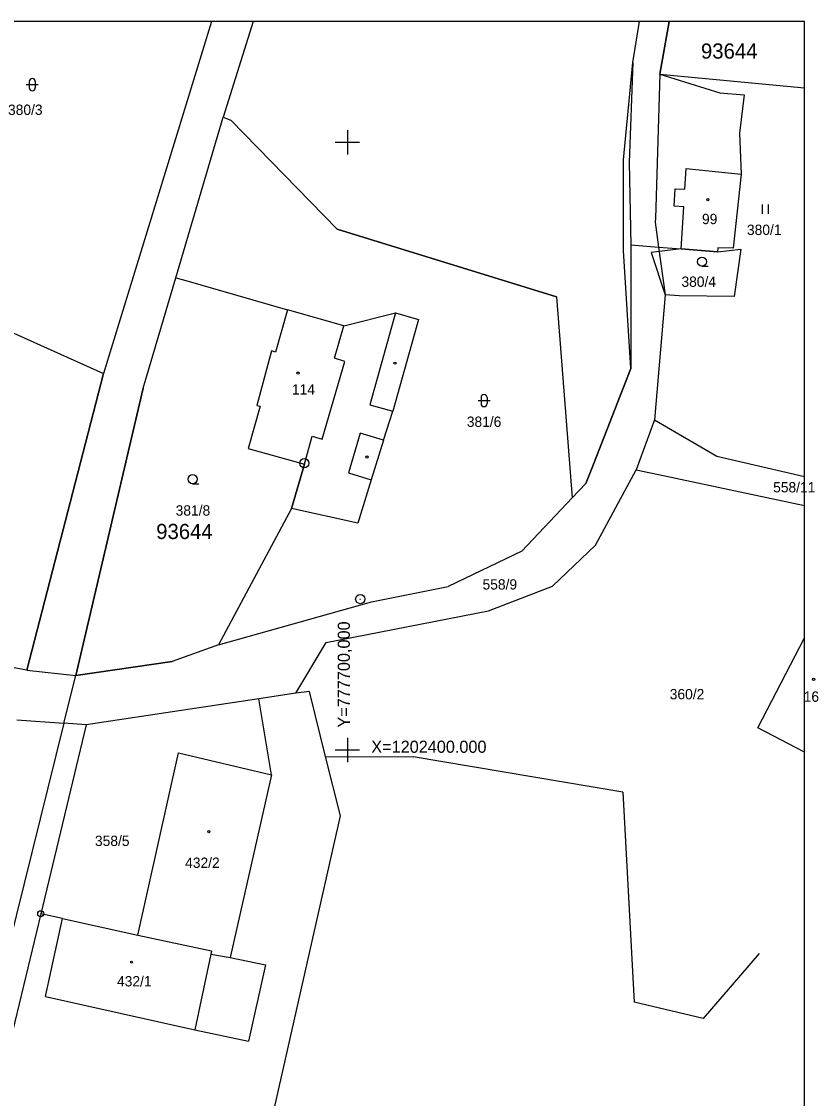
# Model space of a CAD drawing. Extents: x -778045 to -768365, y -1202571 to -1202059.
# Drawn here: x -777753.6 to -777622.5, y -1202457.4 to -1202280.1 of the extents above; entities that cross this region are included whole.
import ezdxf

# ---------------------------------------------------------------- set-up
doc = ezdxf.new("R2010")
doc.units = 0
for name, color, linetype in [('BPEJ', 7, 'Continuous'), ('Katastr_Hranice parcel', 7, 'Continuous'), ('Katastr_Parcelní čísla', 7, 'Continuous'), ('Katastr_Slučkované čáry', 7, 'Continuous'), ('Katastr_Značky kultur', 7, 'Continuous'), ('čtvercová síť', 7, 'Continuous')]:
    doc.layers.add(name, color=color, linetype=linetype)

# ---------------------------------------------------------------- blocks, each defined once
blk = doc.blocks.new('C691')
at = {"layer": 'čtvercová síť'}
for p, q in [((0, 0.5), (0, -0.5)), ((-0.5, 0), (0.5, 0))]:
    blk.add_line(p, q, dxfattribs=at)

msp = doc.modelspace()

# ---------------------------------------------------------------- linework, layer by layer
at = {"layer": 'BPEJ'}
for points in [[(-777715.51, -1202280.12), (-777720.45, -1202295.86), (-777719.2, -1202296.33), (-777701.71, -1202314.27), (-777665.58, -1202325.46), (-777663.01, -1202358.54), (-777660.78, -1202356.18), (-777659.91, -1202353.96), (-777653.34, -1202337.23), (-777654.57, -1202317.8), (-777654.55, -1202302.89), (-777653.05, -1202286.88), (-777651.96, -1202280.12)], [(-777647.08, -1202280.12), (-777648.6, -1202288.78), (-777638.72, -1202291.84), (-777634.69, -1202292.2), (-777635.48, -1202298.47), (-777635.2, -1202305.22), (-777636.54, -1202317.41), (-777639.06, -1202317.35), (-777639.1, -1202318), (-777645.06, -1202317.53), (-777650.01, -1202318.12), (-777647.71, -1202325.12), (-777649.49, -1202345.7), (-777639.21, -1202351.67), (-777624.79, -1202354.99)], [(-777788.3, -1202316.49), (-777774.01, -1202322.88), (-777740.14, -1202338.03), (-777752.8, -1202386.89), (-777773.14, -1202383.15), (-777779.27, -1202388.61), (-777811.7, -1202375.6), (-777805.7, -1202356.3), (-777793.87, -1202330.63), (-777788.3, -1202316.49)], [(-777728.24, -1202322.3), (-777726.98, -1202322.66), (-777709.85, -1202327.57), (-777711.82, -1202334.53), (-777712.49, -1202334.34), (-777714.9, -1202343.3), (-777714.35, -1202343.45), (-777716.32, -1202350.41), (-777707.07, -1202352.95), (-777709.23, -1202360.29), (-777721.22, -1202382.72), (-777728.85, -1202385.43), (-777744.73, -1202387.77), (-777733.6, -1202340.49), (-777728.24, -1202322.3)]]:
    msp.add_lwpolyline(points, dxfattribs=at)
at = {"layer": 'Defpoints'}
for p, q in [((-777624.79, -1202280.12), (-778044.79, -1202280.12)), ((-777624.79, -1202569.12), (-777624.79, -1202280.12))]:
    msp.add_line(p, q, dxfattribs=at)
at = {"layer": 'Katastr_Hranice parcel'}
for p, q in [((-777648.6, -1202288.78), (-777624.79, -1202291.01)), ((-777714.61, -1202391.58), (-777743, -1202395.86)), ((-777708.49, -1202390.66), (-777714.61, -1202391.58)), ((-777712.49, -1202404.11), (-777714.61, -1202391.58)), ((-777743, -1202395.86), (-777750.49, -1202426.97)), ((-777750.49, -1202426.97), (-777772.39, -1202517.89)), ((-777746.91, -1202427.75), (-777750.49, -1202426.97))]:
    msp.add_line(p, q, dxfattribs=at)
for points in [[(-777722.39, -1202280.12), (-777740.14, -1202338.03)], [(-777715.51, -1202280.12), (-777720.45, -1202295.86)], [(-777653.05, -1202286.88), (-777651.96, -1202280.12)], [(-777648.6, -1202288.78), (-777647.08, -1202280.12)], [(-777653.05, -1202286.88), (-777653.66, -1202303.32)], [(-777648.6, -1202288.78), (-777649.33, -1202312.52)], [(-777648.6, -1202288.78), (-777638.72, -1202291.84)], [(-777638.72, -1202291.84), (-777634.69, -1202292.2)], [(-777634.69, -1202292.2), (-777635.48, -1202298.47)], [(-777728.24, -1202322.3), (-777720.45, -1202295.86)], [(-777720.45, -1202295.86), (-777719.2, -1202296.33)], [(-777701.71, -1202314.27), (-777719.2, -1202296.33)], [(-777635.48, -1202298.47), (-777635.2, -1202305.22)], [(-777653.66, -1202303.32), (-777653.34, -1202316.88)], [(-777635.2, -1202305.22), (-777636.54, -1202317.41)], [(-777649.33, -1202312.52), (-777649.34, -1202313.17), (-777648.79, -1202317.24)], [(-777665.58, -1202325.46), (-777701.71, -1202314.27)], [(-777653.34, -1202316.88), (-777653.34, -1202337.23)], [(-777653.34, -1202316.88), (-777648.79, -1202317.24)], [(-777648.79, -1202317.24), (-777645.06, -1202317.53)], [(-777648.79, -1202317.24), (-777647.71, -1202325.12)], [(-777645.06, -1202317.53), (-777639.1, -1202318)], [(-777639.06, -1202317.35), (-777639.1, -1202318)], [(-777639.1, -1202318), (-777635.26, -1202317.6)], [(-777636.54, -1202317.41), (-777639.06, -1202317.35)], [(-777635.26, -1202317.6), (-777636.36, -1202325.39)], [(-777774.01, -1202322.88), (-777740.14, -1202338.03)], [(-777733.6, -1202340.49), (-777728.24, -1202322.3)], [(-777728.24, -1202322.3), (-777726.98, -1202322.66)], [(-777726.98, -1202322.66), (-777709.85, -1202327.57)], [(-777665.58, -1202325.46), (-777663.01, -1202358.54)], [(-777647.71, -1202325.12), (-777649.49, -1202345.7)], [(-777645.43, -1202325.29), (-777647.71, -1202325.12)], [(-777636.36, -1202325.39), (-777645.43, -1202325.29)], [(-777709.85, -1202327.57), (-777711.82, -1202334.53)], [(-777700.6, -1202330.22), (-777709.85, -1202327.57)], [(-777700.6, -1202330.22), (-777692.1, -1202328.08)], [(-777692.1, -1202328.08), (-777688.3, -1202329.15)], [(-777688.3, -1202329.15), (-777692.54, -1202344.26)], [(-777712.49, -1202334.34), (-777714.9, -1202343.3)], [(-777711.82, -1202334.53), (-777712.49, -1202334.34)], [(-777653.34, -1202337.23), (-777659.91, -1202353.96)], [(-777752.8, -1202386.89), (-777740.14, -1202338.03)], [(-777733.6, -1202340.49), (-777744.73, -1202387.77)], [(-777714.35, -1202343.45), (-777716.32, -1202350.41)], [(-777714.9, -1202343.3), (-777714.35, -1202343.45)], [(-777694.06, -1202349.02), (-777692.54, -1202344.26)], [(-777649.49, -1202345.7), (-777652.48, -1202353.91)], [(-777649.49, -1202345.7), (-777639.21, -1202351.67)], [(-777694.06, -1202349.02), (-777696.1, -1202355.56)], [(-777716.32, -1202350.41), (-777707.07, -1202352.95)], [(-777709.23, -1202360.29), (-777707.07, -1202352.95)], [(-777639.21, -1202351.67), (-777624.79, -1202354.99)], [(-777659.91, -1202353.96), (-777660.78, -1202356.18)], [(-777659.17, -1202366.28), (-777652.48, -1202353.91)], [(-777652.48, -1202353.91), (-777647.75, -1202354.88)], [(-777647.75, -1202354.88), (-777624.79, -1202359.75)], [(-777696.1, -1202355.56), (-777698.31, -1202362.67)], [(-777660.78, -1202356.18), (-777663.01, -1202358.54)], [(-777663.01, -1202358.54), (-777671.31, -1202367.29)], [(-777709.23, -1202360.29), (-777721.22, -1202382.72)], [(-777698.31, -1202362.67), (-777709.23, -1202360.29)], [(-777671.31, -1202367.29), (-777683.45, -1202373.1)], [(-777666.24, -1202373.06), (-777659.17, -1202366.28)], [(-777696.04, -1202375.65), (-777683.45, -1202373.1)], [(-777676.8, -1202377.11), (-777666.24, -1202373.06)], [(-777721.22, -1202382.72), (-777696.04, -1202375.65)], [(-777703.53, -1202382.3), (-777676.8, -1202377.11)], [(-777632.44, -1202396.39), (-777624.79, -1202381.58)], [(-777752.8, -1202386.89), (-777773.14, -1202383.15)], [(-777721.22, -1202382.72), (-777728.85, -1202385.43)], [(-777708.49, -1202390.66), (-777703.53, -1202382.3)], [(-777752.8, -1202386.89), (-777744.73, -1202387.77)], [(-777744.73, -1202387.77), (-777728.85, -1202385.43)], [(-777746.67, -1202395.6), (-777744.73, -1202387.77)], [(-777706.27, -1202390.41), (-777708.49, -1202390.66)], [(-777703.6, -1202401.08), (-777706.27, -1202390.41)], [(-777746.67, -1202395.6), (-777776.75, -1202516.88)], [(-777754.4, -1202395.04), (-777746.67, -1202395.6)], [(-777743, -1202395.86), (-777746.67, -1202395.6)], [(-777624.79, -1202400.38), (-777632.44, -1202396.39)], [(-777734.48, -1202430.48), (-777727.79, -1202400.47)], [(-777727.79, -1202400.47), (-777712.49, -1202404.11)], [(-777701.15, -1202410.88), (-777703.6, -1202401.08)], [(-777703.6, -1202401.08), (-777689.17, -1202401.13)], [(-777654.68, -1202406.95), (-777689.17, -1202401.13)], [(-777712.49, -1202404.11), (-777719.28, -1202434.19)], [(-777654.68, -1202406.95), (-777652.82, -1202441.51)], [(-777727.56, -1202527.62), (-777701.15, -1202410.88)], [(-777749.69, -1202440.6), (-777746.91, -1202427.75)], [(-777746.91, -1202427.75), (-777734.48, -1202430.48)], [(-777734.48, -1202430.48), (-777722.37, -1202433.08)], [(-777722.37, -1202433.08), (-777722.48, -1202433.61)], [(-777722.48, -1202433.61), (-777719.28, -1202434.19)], [(-777719.28, -1202434.19), (-777713.51, -1202435.38)], [(-777632.26, -1202433.53), (-777641.45, -1202444.21)], [(-777713.51, -1202435.38), (-777716.29, -1202447.95)], [(-777749.69, -1202440.6), (-777725.13, -1202446.07)], [(-777641.45, -1202444.21), (-777652.82, -1202441.51)], [(-777725.13, -1202446.07), (-777716.29, -1202447.95)]]:
    msp.add_lwpolyline(points, dxfattribs=at)
at = {"layer": 'Katastr_Slučkované čáry'}
for points in [[(-777644.45, -1202307.69), (-777644.24, -1202304.29)], [(-777644.24, -1202304.29), (-777635.2, -1202305.22)], [(-777646.22, -1202310.52), (-777646.07, -1202307.64)], [(-777646.07, -1202307.64), (-777644.45, -1202307.69)], [(-777644.63, -1202310.61), (-777646.22, -1202310.52)], [(-777645.06, -1202317.53), (-777644.63, -1202310.61)], [(-777692.1, -1202328.08), (-777696.34, -1202343.19)], [(-777702.13, -1202335.55), (-777700.6, -1202330.22)], [(-777700.46, -1202336.06), (-777702.13, -1202335.55)], [(-777704.14, -1202348.88), (-777700.46, -1202336.06)], [(-777696.34, -1202343.19), (-777692.54, -1202344.26)], [(-777697.89, -1202347.88), (-777699.83, -1202354.38)], [(-777694.06, -1202349.02), (-777697.89, -1202347.88)], [(-777707.07, -1202352.95), (-777705.8, -1202348.34)], [(-777705.8, -1202348.34), (-777704.14, -1202348.88)], [(-777699.83, -1202354.38), (-777696.1, -1202355.56)], [(-777722.48, -1202433.61), (-777725.13, -1202446.07)]]:
    msp.add_lwpolyline(points, dxfattribs=at)
at = {"layer": 'Katastr_Značky kultur'}
for p, q in [((-777752.89, -1202290.51), (-777750.89, -1202290.51)), ((-777752.39, -1202290.01), (-777752.39, -1202291.01)), ((-777751.39, -1202290.01), (-777751.39, -1202291.01)), ((-777631.73, -1202310.25), (-777631.73, -1202311.75)), ((-777630.73, -1202311.75), (-777630.73, -1202310.25)), ((-777641.65, -1202320.41), (-777640.65, -1202320.41)), ((-777678.51, -1202342.5), (-777676.51, -1202342.5)), ((-777678.01, -1202342), (-777678.01, -1202343)), ((-777677.01, -1202342), (-777677.01, -1202343)), ((-777707.14, -1202352.82), (-777707.04, -1202352.82)), ((-777725.48, -1202356.19), (-777724.48, -1202356.19)), ((-777697.95, -1202375.18), (-777697.85, -1202375.18)), ((-777750.54, -1202426.97), (-777750.44, -1202426.97))]:
    msp.add_line(p, q, dxfattribs=at)
for centre, radius in [((-777640.68, -1202309.44), 0.175), ((-777641.65, -1202319.66), 0.75), ((-777692.19, -1202336.36), 0.175), ((-777708.15, -1202337.98), 0.175), ((-777707.09, -1202352.82), 0.756), ((-777696.79, -1202351.8), 0.175), ((-777725.48, -1202355.44), 0.75), ((-777697.9, -1202375.18), 0.756), ((-777623.28, -1202388.38), 0.175), ((-777722.82, -1202413.45), 0.175), ((-777750.49, -1202426.97), 0.499), ((-777735.54, -1202434.94), 0.175)]:
    msp.add_circle(centre, radius, dxfattribs=at)
for centre, start, end in [((-777751.89, -1202290.01), 0, 180), ((-777751.89, -1202291.01), 180, 0), ((-777677.51, -1202342), 0, 180), ((-777677.51, -1202343), 180, 0)]:
    msp.add_arc(centre, 0.5, start, end, dxfattribs=at)

# ---------------------------------------------------------------- block references
at = {"layer": 'čtvercová síť', "xscale": 4, "yscale": 4}
for p in [(-777700, -1202300), (-777700, -1202400)]:
    msp.add_blockref('C691', p, dxfattribs=at)

# ---------------------------------------------------------------- texts
at = {"layer": 'BPEJ'}
for p in [(-777641.82, -1202286.23), (-777731.48, -1202365.3)]:
    msp.add_text('93644', height=2.5, dxfattribs=at).set_placement(p)
at = {"layer": 'Katastr_Parcelní čísla'}
for s, p in [('380/3', (-777755.87, -1202295.49)), ('99', (-777641.65, -1202313.47)), ('380/1', (-777634.25, -1202315.25)), ('380/4', (-777645.03, -1202323.79)), ('114', (-777709.13, -1202341.52)), ('381/6', (-777680.36, -1202346.84)), ('558/11', (-777629.94, -1202357.62)), ('381/8', (-777728.28, -1202361.44)), ('558/9', (-777677.77, -1202373.61)), ('360/2', (-777646.96, -1202391.68)), ('16', (-777624.91, -1202392.08)), ('358/5', (-777741.56, -1202415.82)), ('432/2', (-777726.72, -1202419.42)), ('432/1', (-777737.93, -1202438.93))]:
    msp.add_text(s, height=1.7, dxfattribs=at).set_placement(p)
at = {"layer": 'čtvercová síť'}
msp.add_text('Y=777700,000', height=2, rotation=90, dxfattribs=at).set_placement((-777699.61, -1202396.33))
msp.add_text('X=1202400.000', height=2, dxfattribs=at).set_placement((-777696.08, -1202400.48))

doc.saveas('drawing.dxf')
